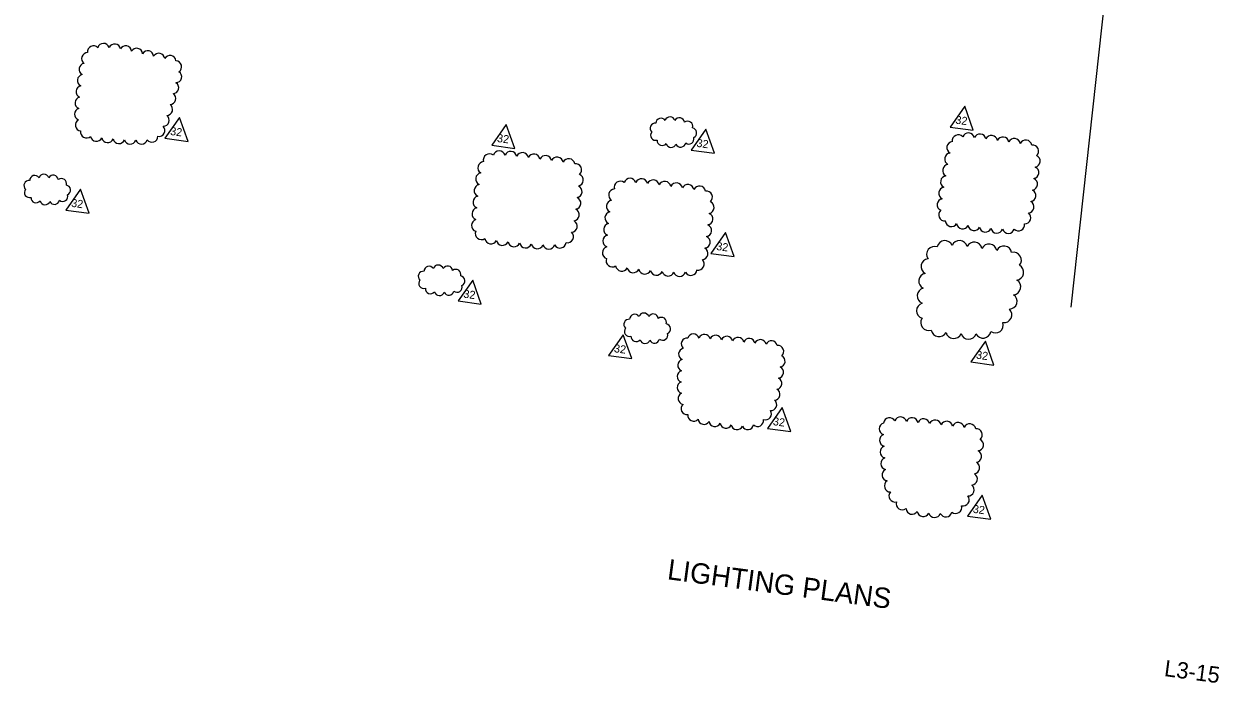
# Model space of a CAD drawing. Extents: x 925493 to 926837, y 636307 to 637171.
# Drawn here: x 926153 to 926741, y 636307 to 636631 of the extents above; entities that cross this region are included whole.
import ezdxf

# ---------------------------------------------------------------- set-up
doc = ezdxf.new("R2010")
doc.units = 0
for name, color, linetype in [('Cloud_dp', 7, 'Continuous'), ('MatchLines_dp', 7, 'Continuous'), ('TextMisc', 7, 'Continuous'), ('TextShtNo', 7, 'Continuous')]:
    doc.layers.add(name, color=color, linetype=linetype)

msp = doc.modelspace()

# ---------------------------------------------------------------- linework, layer by layer
at = {"layer": 'Cloud_dp'}
for points in [[(926615.65, 636590.27), (926608.45, 636580.01), (926619.9, 636578.48)], [(926229.32, 636584.72), (926222.12, 636574.46), (926233.57, 636572.93)], [(926390.13, 636581.29), (926382.94, 636571.02), (926394.39, 636569.49)], [(926488.27, 636578.89), (926481.08, 636568.62), (926492.53, 636567.09)], [(926180.61, 636549.41), (926173.41, 636539.15), (926184.86, 636537.62)], [(926497.99, 636528.14), (926490.79, 636517.88), (926502.25, 636516.35)], [(926373.58, 636504.72), (926366.38, 636494.46), (926377.83, 636492.93)], [(926447.68, 636477.89), (926440.48, 636467.63), (926451.93, 636466.1)], [(926625.81, 636474.72), (926618.62, 636464.45), (926630.07, 636462.93)], [(926525.87, 636442.03), (926518.67, 636431.76), (926530.12, 636430.23)], [(926624.23, 636398.93), (926617.03, 636388.67), (926628.48, 636387.14)]]:
    msp.add_lwpolyline(points, close=True, dxfattribs=at)
for centre, radius, start, end in [((926184.11, 636613.67), 2.93, 89.64779, 234.64779), ((926187.02, 636617), 2.93, 43.00255, 188.00255), ((926191.97, 636618.19), 2.93, 18.9484, 163.9484), ((926197.4, 636617.91), 2.93, 10.21856, 155.21856), ((926202.83, 636617), 2.93, 5.71928, 150.71928), ((926208.27, 636615.81), 2.93, 4.64906, 149.64906), ((926213.71, 636614.58), 2.93, 4.82073, 149.82073), ((926219.16, 636613.37), 2.93, 5.144, 150.144), ((926182.83, 636608.39), 2.93, 98.2171, 243.2171), ((926224.65, 636612.23), 2.93, 6.39869, 151.39869), ((926227.46, 636609.63), 2.93, 303.14559, 88.14559), ((926182.03, 636602.89), 2.93, 100.18753, 245.18753), ((926227.49, 636604.72), 2.93, 272.41999, 57.41999), ((926181.38, 636597.37), 2.93, 101.47886, 246.47886), ((926226.03, 636599.33), 2.93, 272.41999, 57.41999), ((926180.86, 636591.83), 2.93, 102.7728, 247.7728), ((926224.57, 636593.95), 2.93, 272.11234, 57.11234), ((926180.6, 636586.32), 2.93, 106.77912, 251.77912), ((926223.04, 636588.6), 2.93, 270.96245, 55.96245), ((926181.05, 636580.96), 2.93, 117.8435, 262.8435), ((926221.36, 636583.31), 2.93, 268.76697, 53.76697), ((926463.37, 636579.4), 2.51, 82.67056, 227.67056), ((926466.2, 636581.86), 2.51, 34.10765, 179.10765), ((926470.67, 636582.48), 2.51, 16.71694, 161.71694), ((926475.3, 636582.02), 2.51, 6.96113, 151.96113), ((926479.34, 636580.34), 2.51, 342.91745, 127.91745), ((926183.56, 636577.5), 2.92, 169.08529, 314.08529), ((926188.48, 636575.89), 2.93, 189.65288, 334.65288), ((926215.81, 636575.44), 2.93, 214.76349, 359.76349), ((926219.23, 636578.31), 2.92, 260.18845, 45.18845), ((926463.63, 636575.97), 2.51, 141.30835, 286.30835), ((926481.29, 636577.13), 2.51, 294.76198, 79.76198), ((926612.5, 636573.16), 2.99, 42.01994, 187.01994), ((926617.5, 636574.08), 2.99, 13.62028, 158.62028), ((926623.13, 636573.57), 2.99, 11.03451, 156.03451), ((926628.77, 636572.87), 2.99, 9.96477, 154.96477), ((926634.42, 636572.12), 2.99, 9.89674, 154.89674), ((926193.98, 636575.25), 2.93, 192.20042, 337.20042), ((926199.53, 636574.8), 2.93, 193.45024, 338.45024), ((926205.07, 636574.51), 2.93, 195.48294, 340.48294), ((926210.58, 636574.53), 2.93, 199.99861, 344.99861), ((926466.85, 636573.42), 2.51, 176.73132, 321.73132), ((926471.26, 636572.49), 2.51, 194.62704, 339.62704), ((926475.91, 636572.64), 2.52, 203.8708, 348.8708), ((926479.94, 636574.12), 2.51, 231.69605, 16.69605), ((926609.88, 636569.83), 2.99, 96.52923, 241.52923), ((926640.07, 636571.37), 2.99, 9.89674, 154.89674), ((926645.71, 636570.61), 2.99, 9.89674, 154.89674), ((926649.02, 636568.16), 2.99, 311.95437, 96.95437), ((926381.84, 636563.8), 3.02, 50.61787, 195.61787), ((926386.63, 636565.22), 3.02, 17.4207, 162.4207), ((926392.31, 636564.99), 3.02, 12.84487, 157.84487), ((926398, 636564.42), 3.02, 10.75264, 155.75264), ((926403.7, 636563.7), 3.02, 9.9042, 154.9042), ((926409.4, 636562.94), 3.02, 9.89674, 154.89674), ((926415.11, 636562.18), 3.02, 9.89674, 154.89674), ((926420.81, 636561.42), 3.02, 9.89674, 154.89674), ((926608.82, 636564.24), 2.99, 97.03514, 242.03514), ((926649.8, 636563.21), 2.99, 280.96364, 65.96364), ((926378.06, 636554.41), 3.02, 99.0579, 244.0579), ((926379.14, 636559.98), 3.02, 93.89342, 238.89342), ((926424.17, 636558.94), 3.02, 312.35018, 97.35018), ((926607.79, 636558.64), 2.99, 97.21661, 242.21661), ((926649.15, 636557.55), 2.99, 280.96364, 65.96364), ((926155.3, 636551.23), 2.51, 82.67056, 227.67056), ((926158.14, 636553.68), 2.51, 34.10765, 179.10765), ((926162.61, 636554.3), 2.51, 16.71694, 161.71694), ((926167.23, 636553.85), 2.51, 6.96113, 151.96113), ((926171.27, 636552.17), 2.51, 342.91745, 127.91745), ((926173.23, 636548.95), 2.51, 294.76198, 79.76198), ((926377.32, 636548.74), 3.02, 101.16289, 246.16289), ((926425, 636553.95), 3.02, 281.43838, 66.43838), ((926446.2, 636550.36), 3.02, 50.61787, 195.61787), ((926450.99, 636551.78), 3.02, 17.4207, 162.4207), ((926456.66, 636551.54), 3.02, 12.84487, 157.84487), ((926462.36, 636550.98), 3.02, 10.75264, 155.75264), ((926468.05, 636550.26), 3.02, 9.9042, 154.9042), ((926473.76, 636549.5), 3.02, 9.89674, 154.89674), ((926479.47, 636548.74), 3.02, 9.89674, 154.89674), ((926606.79, 636553.04), 2.99, 97.52958, 242.52958), ((926648.49, 636551.9), 2.99, 280.69615, 65.69615), ((926155.57, 636547.8), 2.51, 141.30835, 286.30835), ((926171.88, 636545.95), 2.51, 231.69605, 16.69605), ((926376.75, 636543.03), 3.02, 102.30673, 247.30673), ((926424.39, 636548.22), 3.02, 281.43838, 66.43838), ((926443.5, 636546.53), 3.02, 93.89342, 238.89342), ((926485.17, 636547.97), 3.02, 9.89674, 154.89674), ((926488.53, 636545.5), 3.02, 312.35018, 97.35018), ((926605.86, 636547.43), 2.99, 98.65561, 243.65561), ((926647.73, 636546.28), 2.99, 278.96695, 63.96695), ((926158.79, 636545.24), 2.51, 176.73132, 321.73132), ((926163.19, 636544.32), 2.51, 194.62704, 339.62704), ((926167.85, 636544.46), 2.52, 203.8708, 348.8708), ((926376.29, 636537.31), 3.02, 103.49661, 248.49661), ((926423.76, 636542.51), 3.02, 281.03966, 66.03966), ((926442.41, 636540.97), 3.02, 99.0579, 244.0579), ((926489.36, 636540.5), 3.02, 281.43838, 66.43838), ((926605.11, 636541.82), 2.99, 101.08955, 246.08955), ((926646.74, 636540.72), 2.99, 275.7337, 60.7337), ((926376.04, 636531.61), 3.02, 106.55636, 251.55636), ((926422, 636531.23), 3.02, 275.1742, 60.1742), ((926423.02, 636536.83), 3.02, 279.07576, 64.07576), ((926441.68, 636535.3), 3.02, 101.16289, 246.16289), ((926488.75, 636534.78), 3.02, 281.43838, 66.43838), ((926605.84, 636536.82), 2.99, 130.59031, 275.59031), ((926609.11, 636534.07), 2.99, 184.15629, 329.15629), ((926645.21, 636535.39), 2.99, 267.31905, 52.31905), ((926377.9, 636527.66), 3.02, 158.78686, 303.78686), ((926420.13, 636526.11), 3.02, 259.70946, 44.70946), ((926441.1, 636529.59), 3.02, 102.30673, 247.30673), ((926488.12, 636529.07), 3.02, 281.03966, 66.03966), ((926614.64, 636532.95), 2.99, 187.93693, 332.93693), ((926620.24, 636532.08), 2.99, 189.38982, 334.38982), ((926625.87, 636531.34), 2.99, 190.77054, 335.77054), ((926631.5, 636530.81), 2.99, 193.42, 338.42), ((926637.11, 636530.68), 2.99, 198.86904, 343.86904), ((926642.12, 636531.93), 2.99, 224.1209, 9.1209), ((926382.56, 636525.59), 3.02, 188.38205, 333.38205), ((926388.22, 636524.79), 3.02, 190.5041, 335.5041), ((926393.93, 636524.14), 3.02, 191.5042, 336.5042), ((926399.64, 636523.59), 3.02, 192.46684, 337.46684), ((926405.35, 636523.17), 3.02, 194.16325, 339.16325), ((926411.05, 636523), 3.02, 197.33558, 342.33558), ((926416.59, 636523.5), 3.02, 208.09183, 353.09183), ((926440.64, 636523.87), 3.02, 103.49661, 248.49661), ((926487.38, 636523.39), 3.02, 279.07576, 64.07576), ((926605.92, 636520.27), 3.87, 22.94592, 167.94592), ((926613.07, 636520.33), 3.87, 13.03061, 158.03061), ((926620.34, 636519.56), 3.87, 9.97073, 154.97073), ((926627.64, 636518.59), 3.87, 9.89674, 154.89674), ((926440.4, 636518.17), 3.02, 106.55636, 251.55636), ((926486.35, 636517.79), 3.02, 275.1742, 60.1742), ((926600.8, 636517.45), 3.86, 69.67515, 214.67515), ((926634.95, 636517.62), 3.87, 9.89674, 154.89674), ((926639.7, 636514.53), 3.86, 319.03047, 104.03047), ((926352.15, 636509), 2.51, 34.10765, 179.10765), ((926356.62, 636509.63), 2.51, 16.71694, 161.71694), ((926361.24, 636509.17), 2.51, 6.96113, 151.96113), ((926442.25, 636514.21), 3.02, 158.78686, 303.78686), ((926446.91, 636512.15), 3.02, 188.38205, 333.38205), ((926452.58, 636511.35), 3.02, 190.5041, 335.5041), ((926484.48, 636512.66), 3.02, 259.70946, 44.70946), ((926598.03, 636511.41), 3.87, 96.14277, 241.14277), ((926640.81, 636508.58), 3.87, 277.15881, 62.15881), ((926349.31, 636506.55), 2.51, 82.67056, 227.67056), ((926349.58, 636503.12), 2.51, 141.30835, 286.30835), ((926365.28, 636507.49), 2.51, 342.91745, 127.91745), ((926367.24, 636504.28), 2.51, 294.76198, 79.76198), ((926458.28, 636510.7), 3.02, 191.5042, 336.5042), ((926464, 636510.15), 3.02, 192.46684, 337.46684), ((926469.71, 636509.73), 3.02, 194.16325, 339.16325), ((926475.41, 636509.55), 3.02, 197.33558, 342.33558), ((926480.95, 636510.06), 3.02, 208.09183, 353.09183), ((926596.88, 636504.22), 3.87, 100.66821, 245.66821), ((926639.37, 636501.39), 3.87, 275.21037, 60.21037), ((926352.8, 636500.56), 2.51, 176.73132, 321.73132), ((926357.2, 636499.64), 2.51, 194.62704, 339.62704), ((926361.86, 636499.78), 2.52, 203.8708, 348.8708), ((926365.89, 636501.27), 2.51, 231.69605, 16.69605), ((926596.16, 636496.94), 3.87, 103.0484, 248.0484), ((926595.85, 636489.65), 3.87, 107.09499, 252.09499), ((926637.56, 636494.34), 3.87, 271.00424, 56.00424), ((926453.33, 636485.41), 2.51, 34.10765, 179.10765), ((926457.8, 636486.03), 2.51, 16.71694, 161.71694), ((926462.42, 636485.58), 2.51, 6.96113, 151.96113), ((926634.99, 636487.65), 3.87, 261.95573, 46.95573), ((926450.49, 636482.96), 2.51, 82.67056, 227.67056), ((926450.76, 636479.53), 2.51, 141.30835, 286.30835), ((926466.46, 636483.9), 2.51, 342.91745, 127.91745), ((926468.42, 636480.68), 2.51, 294.76198, 79.76198), ((926597.86, 636483.79), 3.86, 145.61314, 290.61314), ((926630.79, 636482.58), 3.87, 233.73979, 18.73979), ((926453.98, 636476.97), 2.51, 176.73132, 321.73132), ((926458.38, 636476.05), 2.51, 194.62704, 339.62704), ((926463.04, 636476.19), 2.52, 203.8708, 348.8708), ((926467.07, 636477.68), 2.51, 231.69605, 16.69605), ((926479.09, 636473.34), 2.9, 83.5437, 228.5437), ((926482.17, 636475.32), 2.9, 17.08422, 162.08422), ((926487.64, 636475.12), 2.9, 13.66762, 158.66762), ((926493.14, 636474.7), 2.9, 12.59875, 157.59875), ((926498.63, 636474.2), 2.9, 12.02215, 157.02215), ((926504.13, 636473.67), 2.9, 11.8506, 156.8506), ((926509.63, 636473.12), 2.9, 11.78615, 156.78615), ((926515.13, 636472.56), 2.9, 11.66487, 156.66487), ((926603.04, 636480.73), 3.87, 188.25093, 333.25093), ((926610.26, 636479.85), 3.87, 192.7885, 337.7885), ((926617.54, 636479.51), 3.87, 196.91815, 341.91815), ((926624.68, 636480.03), 3.87, 206.46619, 351.46619), ((926477.79, 636468.34), 2.9, 102.37436, 247.37436), ((926520.62, 636471.98), 2.9, 11.19576, 156.19576), ((926523.75, 636469.66), 2.9, 310.72465, 95.72465), ((926477.39, 636462.85), 2.9, 104.37073, 249.37073), ((926524.39, 636464.85), 2.9, 279.3772, 64.3772), ((926477.15, 636457.35), 2.9, 105.59621, 250.59621), ((926523.61, 636459.38), 2.9, 279.3772, 64.3772), ((926477.13, 636451.87), 2.9, 108.97136, 253.97136), ((926522.83, 636453.9), 2.9, 279.35334, 64.35334), ((926477.58, 636446.48), 2.9, 115.58071, 260.58071), ((926520.27, 636443.41), 2.9, 265.31996, 50.31996), ((926521.86, 636448.53), 2.9, 275.22807, 60.22807), ((926479.04, 636441.46), 2.9, 131.89462, 276.89462), ((926517.64, 636438.89), 2.9, 249.2449, 34.2449), ((926482.27, 636438.26), 2.9, 173.70328, 318.70328), ((926487.33, 636436.65), 2.9, 185.98707, 330.98707), ((926492.74, 636435.65), 2.9, 187.99562, 332.99562), ((926498.18, 636434.79), 2.9, 189.10299, 334.10299), ((926513.77, 636435.61), 2.9, 226.3192, 11.3192), ((926576.63, 636431.58), 2.99, 108.18694, 253.18694), ((926578.67, 636434.05), 2.99, 27.97798, 172.97798), ((926584.12, 636434.42), 2.99, 14.75024, 159.75024), ((926589.78, 636434.05), 2.99, 12.71138, 157.71138), ((926595.44, 636433.52), 2.99, 11.68577, 156.68577), ((926601.11, 636432.93), 2.99, 11.42842, 156.42842), ((926606.78, 636432.33), 2.99, 11.3776, 156.3776), ((926612.45, 636431.71), 2.99, 11.28199, 156.28199), ((926618.12, 636431.08), 2.99, 10.913, 155.913), ((926503.63, 636434.07), 2.9, 190.83466, 335.83466), ((926508.92, 636434.07), 2.9, 204.06194, 349.06194), ((926576.79, 636425.91), 2.99, 109.96416, 254.96416), ((926621.31, 636428.67), 2.99, 309.86597, 94.86597), ((926577.06, 636420.22), 2.99, 110.39896, 255.39896), ((926621.88, 636423.7), 2.99, 278.25639, 63.25639), ((926577.37, 636414.53), 2.99, 110.98684, 255.98684), ((926620.96, 636418.07), 2.99, 278.25639, 63.25639), ((926577.95, 636408.93), 2.99, 115.71763, 260.71763), ((926620.03, 636412.45), 2.99, 278.01935, 63.01935), ((926579.15, 636403.51), 2.99, 124.34436, 269.34436), ((926618.92, 636406.91), 2.99, 274.32275, 59.32275), ((926581.38, 636398.56), 2.99, 139.01726, 284.01726), ((926614.88, 636396.67), 2.99, 254.72263, 39.72263), ((926617.32, 636401.56), 2.99, 267.29245, 52.29245), ((926584.96, 636394.77), 2.99, 162.69963, 307.69963), ((926611.21, 636392.98), 2.99, 230.61383, 15.61383), ((926589.77, 636392.55), 2.99, 182.77115, 327.77115), ((926595.25, 636391.44), 2.99, 189.31961, 334.31961), ((926600.82, 636390.97), 2.99, 196.08385, 341.08385), ((926606.38, 636391.23), 2.99, 204.16514, 349.16514)]:
    msp.add_arc(centre, radius, start, end, dxfattribs=at)
at = {"layer": 'MatchLines_dp'}
msp.add_line((926729.16, 637046.86), (926667.8, 636491.42), dxfattribs=at)

# ---------------------------------------------------------------- texts
at = {"layer": 'Cloud_dp'}
for p in [(926610.91, 636581.68), (926224.58, 636576.12), (926385.4, 636572.69), (926483.54, 636570.29), (926175.87, 636540.82), (926493.25, 636519.55), (926368.84, 636496.13), (926442.94, 636469.3), (926621.08, 636466.12), (926521.13, 636433.43), (926619.49, 636390.34)]:
    msp.add_text('32', height=3.938, rotation=352.39674, dxfattribs=at).set_placement(p)
at = {"layer": 'TextMisc'}
msp.add_text('        LIGHTING PLANS         ', height=10, rotation=352.39674, dxfattribs=at).set_placement((926439.52, 636361.6))
at = {"layer": 'TextShtNo'}
msp.add_text(' L3-15 ', height=8, rotation=352.39674, dxfattribs=at).set_placement((926710.57, 636310.44))

doc.saveas('drawing.dxf')
